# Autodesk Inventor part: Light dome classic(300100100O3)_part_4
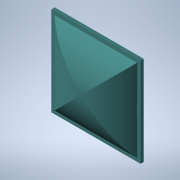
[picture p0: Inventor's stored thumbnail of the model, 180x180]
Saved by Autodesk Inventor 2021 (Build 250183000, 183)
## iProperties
Created: 2026-04
Part Number: Light dome classic(300100100O3)_part_4
Material: Generic
Catalog Web Link: www.3dfindit.com
Description: Light dome classic_part_4-
Vendor: KINGSPAN
Document SubType Name: Modeling
Designer: psAdmin
Manufacturer: KINGSPAN
Mass: 27584.9 g
Surface Area: 18165.8 cm^2
Volume: 27584.9 cm^3
Density: 1 g/cm^3
Appearance: PSOLRGB-194-255-255
Category: PARTsolutions
Company: KINGSPAN
Title: Light dome classic(300100100O3)_part_4
Author: Cadenas PARTsolutions
PSOL_IDENT_0: {$CADENAS_DATA/23d-libs/kingspan_kla/light_dome_classic/parts/part_4.prj},254 {VTYP=3D},{NB=Light do
PSOL_IDENT_1: me classic(300100100O3)_part_4},{LINA=Light dome classic(300100100O3)_part_4},{NN=Light dome classic
PSOL_IDENT_2: _part_4},{DATE=20.03.2025 09:30:52},{GEOMDATE=28.06.2024 08:50:42},{VERSION=},{LINEID=10},{WBVAR=LOD
PSOL_IDENT_3: LEVEL,L,W,TG,TS},{WBNUMERIC=W}  {NB=Light dome classic(300100100O3)_part_4},{LINA=Light dome classic
PSOL_IDENT_4: (300100100O3)_part_4},{KT=DUMMY},{IDNR=},{PN=Light dome classic},{LODLEVEL=300},{L=100},{W=100},{WX=
PSOL_IDENT_5: 100,150,200,250,300},{TG=O},{TS=3},{TSX='3','acrylic shell with Polycarbonate','4','2 layers of acry
PSOL_IDENT_6: lic shell + 1  Polycarbonate panel','5','1 layers of acrylic shell + 1 polycarbonate panel + aerogel'
PSOL_IDENT_7: },{LX=1000},{XWX=1000},{VER=2},{HEI=1048.274},{TOP=300},{NO=2},{HEIGHT=180},{SEC=30}
NB: Light dome classic(300100100O3)_part_4
NN: Light dome classic_part_4
NBSYN: $PN.($LODLEVEL.$L.$W.$TG.$TS.)_part_4
LINA: Light dome classic(300100100O3)_part_4
CATALOG: Light + Air
PN: Light dome classic
LODLEVEL: 300
L: 100
W: 100
TG: opal
TS: acrylic shell with Polycarbonate
SUPPLIER: KINGSPAN
ARTICLENO: Light dome classic(300100100O3)_part_4
BOMINFO: Light dome classic(300100100O3)_part_4
CREATOR: CADENAS GmbH
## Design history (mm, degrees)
sketch "Sketch_9"
  geometry: L1 (400, 0)-(400, 106.946); L2 (-400, 106.946)-(-400, 0); L3 (-400, 0)-(400, 0); A1 r 624.224 centre (0, -372.278) between (400, 106.946) and (-400, 106.946)
  constraints: 6 end point, 2 point on circle, 1 centre point
extrude "Extrusion1" join sketch "Sketch_9" stored distance "d0" = 1000; taper "d1" = 0 deg
sketch "Sketch_2"
  geometry: L1 (506, 103.596)-(-506, 103.596); L2 (-506, 103.596)-(-506, 71.946); L3 (-506, 71.946)-(506, 71.946); L4 (506, 71.946)-(506, 103.596)
  constraints: 8 end point
extrude "Extrusion2" join sketch "Sketch_2" stored distance "d2" = 2000; taper "d3" = 0 deg
sketch "Sketch_3"
  geometry: L1 (-530, 103.596)-(-530, 71.946); L2 (-530, 71.946)-(530, 71.946); L3 (530, 71.946)-(530, 103.596); L4 (530, 103.596)-(-530, 103.596)
  constraints: 8 end point
extrude "Extrusion3" join sketch "Sketch_3" stored distance "d4" = 2000; taper "d5" = 0 deg
sketch "Sketch_4"
  geometry: L1 (-1433, 103.596)-(-1433, -128.054); L2 (-1433, -128.054)-(1433, -128.054); L3 (1433, -128.054)-(1433, 103.596); L4 (1433, 103.596)-(433, 103.596); L5 (433, 103.596)-(433, 71.946); L6 (433, 71.946)-(-433, 71.946); L7 (-433, 71.946)-(-433, 103.596); L8 (-433, 103.596)-(-1433, 103.596)
  constraints: 16 end point
extrude "Extrusion4" cut sketch "Sketch_4" stored distance "d6" = 2000; taper "d7" = 0 deg
sketch "Sketch_12"
  geometry: L1 (500, -531.206)-(-500, -531.206); L2 (-385, 106.946)-(-385, -100); L3 (-385, -100)-(385, -100); L4 (385, -100)-(385, 106.946); A1 r 701.957 centre (0, -480.011) between (385, 106.946) and (-385, 106.946)
  constraints: 8 end point, 2 point on circle, 1 centre point
revolve "Revolution1" sketch "Sketch_12" stored, may be unused: angle "d8" = 360 deg
sketch "Sketch_13"
  geometry: L1 (432, 103.596)-(380, 103.596); L2 (380, 103.596)-(380, 71.946); L3 (380, 71.946)-(-380, 71.946); L4 (-380, 71.946)-(-380, 103.596); L5 (-380, 103.596)-(-432, 103.596); L6 (-432, 103.596)-(-432, 61.946); L7 (-432, 61.946)-(432, 61.946); L8 (432, 61.946)-(432, 103.596)
  constraints: 16 end point
extrude "Extrusion5" join sketch "Sketch_13" stored distance "d9" = 1000; taper "d10" = 0 deg
sketch "Sketch_14"
  geometry: L1 (1400, 103.596)-(432, 103.596); L2 (432, 103.596)-(432, 71.946); L3 (432, 71.946)-(-432, 71.946); L4 (-432, 71.946)-(-432, 103.596); L5 (-432, 103.596)-(-1400, 103.596); L6 (-1400, 103.596)-(-1400, -128.054); L7 (-1400, -128.054)-(1400, -128.054); L8 (1400, -128.054)-(1400, 103.596)
  constraints: 16 end point
extrude "Extrusion6" cut sketch "Sketch_14" stored distance "d11" = 2000; taper "d12" = 0 deg
sketch "Sketch_15"
  geometry: L1 (1424, 1333.333)-(-1424, 1333.333); L2 (-1424, 1333.333)-(-1424, 0); L3 (-1424, 0)-(-433, 0); L4 (-433, 0)-(-433, 103.596); L5 (-433, 103.596)-(-400, 103.596); L6 (-400, 103.596)-(-400, 106.946); L7 (400, 106.946)-(400, 103.596); L8 (400, 103.596)-(433, 103.596); L9 (433, 103.596)-(433, 0); L10 (433, 0)-(1424, 0); L11 (1424, 0)-(1424, 1333.333); A1 r 624.224 centre (0, -372.278) between (400, 106.946) and (-400, 106.946)
  constraints: 22 end point, 2 point on circle, 1 centre point
extrude "Extrusion7" cut sketch "Sketch_15" stored distance "d13" = 1000; taper "d14" = 0 deg
node "IP_4_XY"
node "IP_4_YZ"
node "IP_4_ZX"
node "IP_4_X"
node "IP_4_Y"
node "IP_4_Z"
node "IP_4_Center"
body "Solid1"
